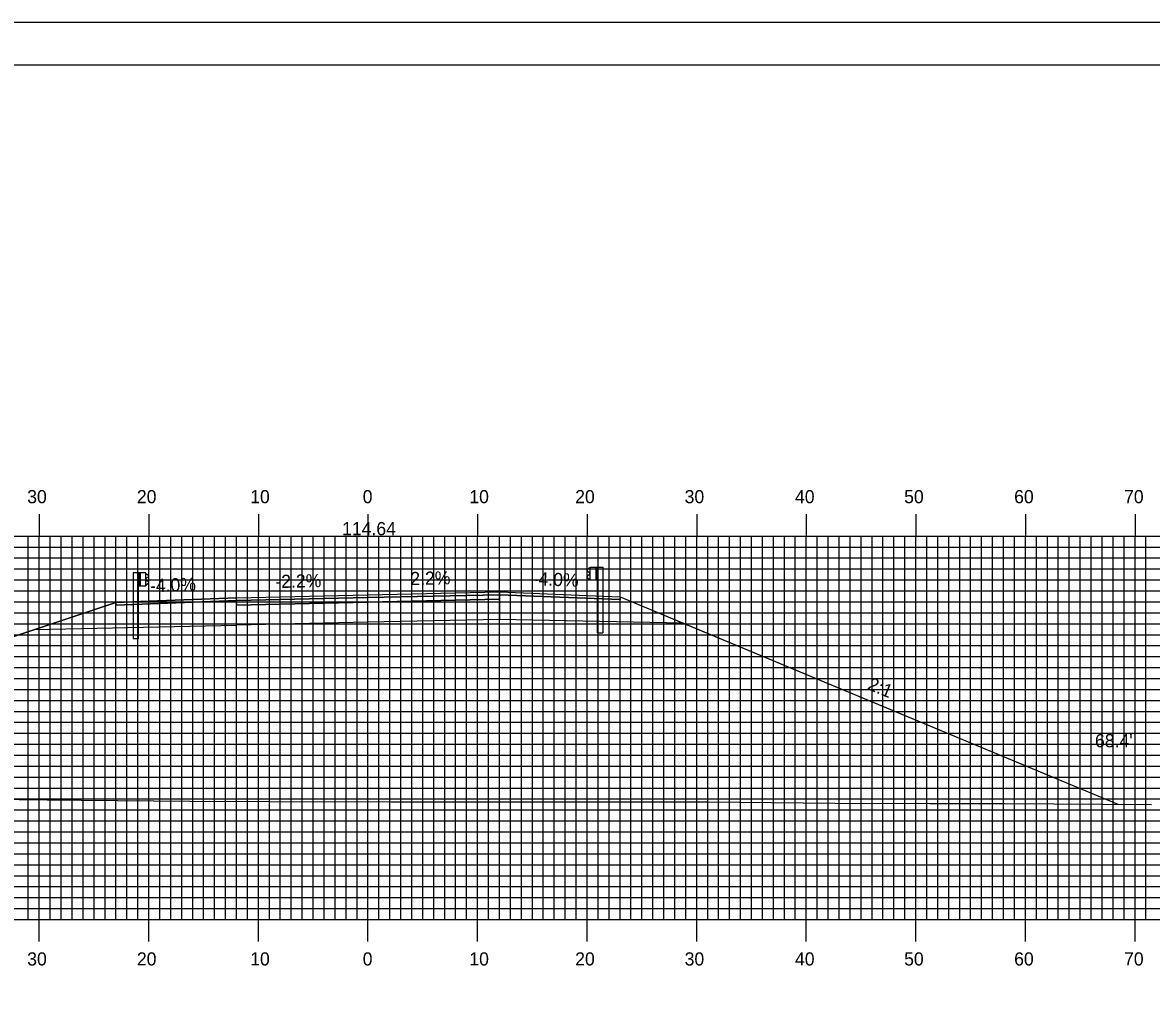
# Model space of a CAD drawing. Extents: x 1786582 to 1786926, y 442591 to 442811.
# Drawn here: x 1786716.6 to 1786819.6, y 442722 to 442810.5 of the extents above; entities that cross this region are included whole.
import ezdxf

# ---------------------------------------------------------------- set-up
doc = ezdxf.new("R2010")
doc.units = 0
for name, color, linetype in [('ANNOTATION', 7, 'Continuous'), ('BORDER', 7, 'Continuous'), ('D_Guardrail_Beam_Lt', 7, 'Continuous'), ('D_Guardrail_Beam_Rt', 7, 'Continuous'), ('D_Roadway_Centerline', 7, 'Continuous'), ('D_Roadway_Centerline_Text', 7, 'Continuous'), ('D_Roadway_Edge_Shoulder', 7, 'Continuous'), ('D_Roadway_Edge_TW', 7, 'Continuous'), ('D_Roadway_Pavement', 7, 'Continuous'), ('D_Roadway_SlopeLines', 7, 'Continuous'), ('D_Roadway_SubGrade', 7, 'Continuous'), ('D_Text_Standard', 7, 'Continuous'), ('H_V ANNOTATION', 7, 'Continuous'), ('MAJOR', 7, 'Continuous'), ('MINOR', 7, 'Continuous'), ('PLOT BOUNDARY', 7, 'Continuous'), ('S_Roadway_Centerline', 7, 'Continuous')]:
    doc.layers.add(name, color=color, linetype=linetype)

msp = doc.modelspace()

# ---------------------------------------------------------------- linework, layer by layer
at = {"layer": 'BORDER'}
msp.add_lwpolyline([(1786598.48, 442596.67), (1786918.48, 442596.67), (1786918.48, 442806.67), (1786598.48, 442806.67)], close=True, dxfattribs=at)
at = {"layer": 'D_Guardrail_Beam_Lt'}
for p, q in [((1786726.65, 442760.3), (1786726.65, 442754.3)), ((1786727.12, 442760.3), (1786726.65, 442760.3)), ((1786727.81, 442760.3), (1786727.12, 442760.3)), ((1786727.12, 442760.3), (1786727.12, 442759.14)), ((1786727.18, 442760.3), (1786727.18, 442759.14)), ((1786727.29, 442760.3), (1786727.29, 442759.14)), ((1786727.81, 442759.14), (1786727.81, 442760.3)), ((1786727.81, 442760.22), (1786727.88, 442760.21)), ((1786727.81, 442759.75), (1786727.81, 442759.68)), ((1786728.04, 442759.96), (1786727.85, 442759.82)), ((1786727.85, 442759.62), (1786728.04, 442759.48)), ((1786727.9, 442760.2), (1786728.04, 442760.1)), ((1786727.12, 442759.14), (1786727.81, 442759.14)), ((1786727.14, 442754.3), (1786727.14, 442759.14)), ((1786727.88, 442759.23), (1786727.81, 442759.22)), ((1786728.04, 442759.34), (1786727.9, 442759.24)), ((1786727.14, 442754.3), (1786726.65, 442754.3))]:
    msp.add_line(p, q, dxfattribs=at)
for centre, major_axis, start_param, end_param in [((1786727.89, 442759.75), (-0.0789, 0), 5.323254, 6.283185), ((1786727.89, 442759.68), (-0.0789, 0), 6.283185, 7.243116), ((1786727.87, 442760.16), (0.0417, 0), 0.959931, 1.376053), ((1786727.99, 442760.03), (0.0877, 0), 5.323254, 7.243116), ((1786727.87, 442759.27), (0.0417, 0), 4.907132, 5.323254), ((1786727.99, 442759.41), (0.0877, 0), 5.323254, 7.243116)]:
    msp.add_ellipse(centre, major_axis=major_axis, ratio=0.995501, start_param=start_param, end_param=end_param, dxfattribs=at)
at = {"layer": 'D_Guardrail_Beam_Rt'}
for p, q in [((1786768.26, 442760.73), (1786768.12, 442760.63)), ((1786768.35, 442760.75), (1786768.27, 442760.73)), ((1786768.35, 442760.83), (1786769.04, 442760.83)), ((1786768.35, 442759.66), (1786768.35, 442760.83)), ((1786768.87, 442760.83), (1786768.87, 442759.66)), ((1786768.97, 442760.83), (1786768.97, 442759.66)), ((1786769.04, 442760.83), (1786769.51, 442760.83)), ((1786769.04, 442760.83), (1786769.04, 442759.66)), ((1786769.51, 442760.83), (1786769.51, 442754.83)), ((1786768.12, 442760.48), (1786768.31, 442760.35)), ((1786768.31, 442760.15), (1786768.12, 442760.01)), ((1786768.12, 442759.87), (1786768.26, 442759.77)), ((1786768.27, 442759.76), (1786768.35, 442759.75)), ((1786768.34, 442760.28), (1786768.34, 442760.21)), ((1786769.04, 442759.66), (1786768.35, 442759.66)), ((1786769.02, 442754.83), (1786769.02, 442759.66)), ((1786769.02, 442754.83), (1786769.51, 442754.83))]:
    msp.add_line(p, q, dxfattribs=at)
for centre, major_axis, start_param, end_param in [((1786768.17, 442760.55), (-0.0877, 0), 5.323254, 7.243116), ((1786768.28, 442760.69), (-0.0417, 0), 4.907132, 5.323254), ((1786768.17, 442759.94), (-0.0877, 0), 5.323254, 7.243116), ((1786768.28, 442759.8), (-0.0417, 0), 0.959931, 1.376053), ((1786768.27, 442760.28), (0.0789, 0), 0, 0.959931), ((1786768.27, 442760.21), (0.0789, 0), 5.323254, 6.283185)]:
    msp.add_ellipse(centre, major_axis=major_axis, ratio=0.995501, start_param=start_param, end_param=end_param, dxfattribs=at)
at = {"layer": 'D_Roadway_Centerline'}
msp.add_lwpolyline([(1786673.07, 442740.26), (1786717.68, 442755.13), (1786725.08, 442757.6), (1786728.08, 442757.72), (1786736.08, 442758.04), (1786748.08, 442758.3), (1786760.08, 442758.57), (1786768.08, 442758.25), (1786771.08, 442758.13), (1786776.83, 442755.73), (1786816.52, 442739.19)], dxfattribs=at)
at = {"layer": 'D_Roadway_Edge_Shoulder'}
for points in [[(1786760.08, 442758.57), (1786768.08, 442758.25), (1786768.08, 442758.25), (1786771.08, 442758.13), (1786771.08, 442757.88), (1786760.08, 442758.32)], [(1786736.08, 442758.04), (1786728.08, 442757.72), (1786728.08, 442757.72), (1786725.08, 442757.6), (1786725.08, 442757.35), (1786736.08, 442757.79)]]:
    msp.add_lwpolyline(points, close=True, dxfattribs=at)
at = {"layer": 'D_Roadway_Edge_TW'}
msp.add_lwpolyline([(1786736.08, 442757.79), (1786736.08, 442758.04), (1786748.08, 442758.3), (1786760.08, 442758.57), (1786760.08, 442758.32), (1786748.08, 442758.05)], close=True, dxfattribs=at)
at = {"layer": 'D_Roadway_Pavement'}
msp.add_lwpolyline([(1786736.08, 442757.37), (1786736.08, 442757.79), (1786748.08, 442758.05), (1786760.08, 442758.32), (1786760.08, 442757.9), (1786748.08, 442757.64)], close=True, dxfattribs=at)
for points in [[(1786736.08, 442757.79), (1786736.08, 442757.37)], [(1786760.08, 442758.32), (1786760.08, 442757.9)]]:
    msp.add_lwpolyline(points, dxfattribs=at)
at = {"layer": 'D_Roadway_SlopeLines'}
for points in [[(1786725.08, 442757.6), (1786670.4, 442739.38)], [(1786771.08, 442758.13), (1786816.52, 442739.19)]]:
    msp.add_lwpolyline(points, dxfattribs=at)
at = {"layer": 'D_Roadway_SubGrade'}
for points in [[(1786736.08, 442757.37), (1786736.08, 442757.79), (1786725.08, 442757.35), (1786725.08, 442757.6), (1786717.68, 442755.13), (1786736.08, 442755.54)], [(1786736.08, 442755.54), (1786736.08, 442757.79), (1786736.08, 442757.37), (1786748.08, 442757.64), (1786760.08, 442757.9), (1786760.08, 442758.32), (1786760.08, 442756.07), (1786748.08, 442755.8)], [(1786760.08, 442757.9), (1786760.08, 442758.32), (1786771.08, 442757.88), (1786771.08, 442758.13), (1786776.83, 442755.73), (1786760.08, 442756.07)]]:
    msp.add_lwpolyline(points, close=True, dxfattribs=at)
at = {"layer": 'MAJOR'}
for p, q in [((1786718.08, 442765.67), (1786718.08, 442763.67)), ((1786728.08, 442765.67), (1786728.08, 442763.67)), ((1786738.08, 442765.67), (1786738.08, 442763.67)), ((1786748.08, 442765.67), (1786748.08, 442763.67)), ((1786758.08, 442765.67), (1786758.08, 442763.67)), ((1786768.08, 442765.67), (1786768.08, 442763.67)), ((1786778.08, 442765.67), (1786778.08, 442763.67)), ((1786788.08, 442765.67), (1786788.08, 442763.67)), ((1786798.08, 442765.67), (1786798.08, 442763.67)), ((1786808.08, 442765.67), (1786808.08, 442763.67)), ((1786818.08, 442765.67), (1786818.08, 442763.67)), ((1786608.08, 442763.67), (1786888.08, 442763.67)), ((1786608.08, 442763.67), (1786888.08, 442763.67)), ((1786718.08, 442728.67), (1786718.08, 442763.67)), ((1786728.08, 442728.67), (1786728.08, 442763.67)), ((1786738.08, 442728.67), (1786738.08, 442763.67)), ((1786748.08, 442728.67), (1786748.08, 442763.67)), ((1786758.08, 442728.67), (1786758.08, 442763.67)), ((1786768.08, 442728.67), (1786768.08, 442763.67)), ((1786778.08, 442728.67), (1786778.08, 442763.67)), ((1786788.08, 442728.67), (1786788.08, 442763.67)), ((1786798.08, 442728.67), (1786798.08, 442763.67)), ((1786808.08, 442728.67), (1786808.08, 442763.67)), ((1786818.08, 442728.67), (1786818.08, 442763.67)), ((1786608.08, 442758.67), (1786888.08, 442758.67)), ((1786608.08, 442753.67), (1786888.08, 442753.67)), ((1786608.08, 442748.67), (1786888.08, 442748.67)), ((1786608.08, 442743.67), (1786888.08, 442743.67)), ((1786608.08, 442738.67), (1786888.08, 442738.67)), ((1786608.08, 442733.67), (1786888.08, 442733.67)), ((1786608.08, 442728.67), (1786888.08, 442728.67)), ((1786608.08, 442728.67), (1786888.08, 442728.67)), ((1786718.08, 442726.66), (1786718.08, 442728.67)), ((1786728.08, 442726.66), (1786728.08, 442728.67)), ((1786738.08, 442726.66), (1786738.08, 442728.67)), ((1786748.08, 442726.66), (1786748.08, 442728.67)), ((1786758.08, 442726.66), (1786758.08, 442728.67)), ((1786768.08, 442726.66), (1786768.08, 442728.67)), ((1786778.08, 442726.66), (1786778.08, 442728.67)), ((1786788.08, 442726.66), (1786788.08, 442728.67)), ((1786798.08, 442726.66), (1786798.08, 442728.67)), ((1786808.08, 442726.66), (1786808.08, 442728.67)), ((1786818.08, 442726.66), (1786818.08, 442728.67))]:
    msp.add_line(p, q, dxfattribs=at)
at = {"layer": 'MINOR'}
for p, q in [((1786608.08, 442762.67), (1786888.08, 442762.67)), ((1786717.08, 442728.67), (1786717.08, 442763.67)), ((1786719.08, 442728.67), (1786719.08, 442763.67)), ((1786720.08, 442728.67), (1786720.08, 442763.67)), ((1786721.08, 442728.67), (1786721.08, 442763.67)), ((1786722.08, 442728.67), (1786722.08, 442763.67)), ((1786723.08, 442728.67), (1786723.08, 442763.67)), ((1786724.08, 442728.67), (1786724.08, 442763.67)), ((1786725.08, 442728.67), (1786725.08, 442763.67)), ((1786726.08, 442728.67), (1786726.08, 442763.67)), ((1786727.08, 442728.67), (1786727.08, 442763.67)), ((1786729.08, 442728.67), (1786729.08, 442763.67)), ((1786730.08, 442728.67), (1786730.08, 442763.67)), ((1786731.08, 442728.67), (1786731.08, 442763.67)), ((1786732.08, 442728.67), (1786732.08, 442763.67)), ((1786733.08, 442728.67), (1786733.08, 442763.67)), ((1786734.08, 442728.67), (1786734.08, 442763.67)), ((1786735.08, 442728.67), (1786735.08, 442763.67)), ((1786736.08, 442728.67), (1786736.08, 442763.67)), ((1786737.08, 442728.67), (1786737.08, 442763.67)), ((1786739.08, 442728.67), (1786739.08, 442763.67)), ((1786740.08, 442728.67), (1786740.08, 442763.67)), ((1786741.08, 442728.67), (1786741.08, 442763.67)), ((1786742.08, 442728.67), (1786742.08, 442763.67)), ((1786743.08, 442728.67), (1786743.08, 442763.67)), ((1786744.08, 442728.67), (1786744.08, 442763.67)), ((1786745.08, 442728.67), (1786745.08, 442763.67)), ((1786746.08, 442728.67), (1786746.08, 442763.67)), ((1786747.08, 442728.67), (1786747.08, 442763.67)), ((1786749.08, 442728.67), (1786749.08, 442763.67)), ((1786750.08, 442728.67), (1786750.08, 442763.67)), ((1786751.08, 442728.67), (1786751.08, 442763.67)), ((1786752.08, 442728.67), (1786752.08, 442763.67)), ((1786753.08, 442728.67), (1786753.08, 442763.67)), ((1786754.08, 442728.67), (1786754.08, 442763.67)), ((1786755.08, 442728.67), (1786755.08, 442763.67)), ((1786756.08, 442728.67), (1786756.08, 442763.67)), ((1786757.08, 442728.67), (1786757.08, 442763.67)), ((1786759.08, 442728.67), (1786759.08, 442763.67)), ((1786760.08, 442728.67), (1786760.08, 442763.67)), ((1786761.08, 442728.67), (1786761.08, 442763.67)), ((1786762.08, 442728.67), (1786762.08, 442763.67)), ((1786763.08, 442728.67), (1786763.08, 442763.67)), ((1786764.08, 442728.67), (1786764.08, 442763.67)), ((1786765.08, 442728.67), (1786765.08, 442763.67)), ((1786766.08, 442728.67), (1786766.08, 442763.67)), ((1786767.08, 442728.67), (1786767.08, 442763.67)), ((1786769.08, 442728.67), (1786769.08, 442763.67)), ((1786770.08, 442728.67), (1786770.08, 442763.67)), ((1786771.08, 442728.67), (1786771.08, 442763.67)), ((1786772.08, 442728.67), (1786772.08, 442763.67)), ((1786773.08, 442728.67), (1786773.08, 442763.67)), ((1786774.08, 442728.67), (1786774.08, 442763.67)), ((1786775.08, 442728.67), (1786775.08, 442763.67)), ((1786776.08, 442728.67), (1786776.08, 442763.67)), ((1786777.08, 442728.67), (1786777.08, 442763.67)), ((1786779.08, 442728.67), (1786779.08, 442763.67)), ((1786780.08, 442728.67), (1786780.08, 442763.67)), ((1786781.08, 442728.67), (1786781.08, 442763.67)), ((1786782.08, 442728.67), (1786782.08, 442763.67)), ((1786783.08, 442728.67), (1786783.08, 442763.67)), ((1786784.08, 442728.67), (1786784.08, 442763.67)), ((1786785.08, 442728.67), (1786785.08, 442763.67)), ((1786786.08, 442728.67), (1786786.08, 442763.67)), ((1786787.08, 442728.67), (1786787.08, 442763.67)), ((1786789.08, 442728.67), (1786789.08, 442763.67)), ((1786790.08, 442728.67), (1786790.08, 442763.67)), ((1786791.08, 442728.67), (1786791.08, 442763.67)), ((1786792.08, 442728.67), (1786792.08, 442763.67)), ((1786793.08, 442728.67), (1786793.08, 442763.67)), ((1786794.08, 442728.67), (1786794.08, 442763.67)), ((1786795.08, 442728.67), (1786795.08, 442763.67)), ((1786796.08, 442728.67), (1786796.08, 442763.67)), ((1786797.08, 442728.67), (1786797.08, 442763.67)), ((1786799.08, 442728.67), (1786799.08, 442763.67)), ((1786800.08, 442728.67), (1786800.08, 442763.67)), ((1786801.08, 442728.67), (1786801.08, 442763.67)), ((1786802.08, 442728.67), (1786802.08, 442763.67)), ((1786803.08, 442728.67), (1786803.08, 442763.67)), ((1786804.08, 442728.67), (1786804.08, 442763.67)), ((1786805.08, 442728.67), (1786805.08, 442763.67)), ((1786806.08, 442728.67), (1786806.08, 442763.67)), ((1786807.08, 442728.67), (1786807.08, 442763.67)), ((1786809.08, 442728.67), (1786809.08, 442763.67)), ((1786810.08, 442728.67), (1786810.08, 442763.67)), ((1786811.08, 442728.67), (1786811.08, 442763.67)), ((1786812.08, 442728.67), (1786812.08, 442763.67)), ((1786813.08, 442728.67), (1786813.08, 442763.67)), ((1786814.08, 442728.67), (1786814.08, 442763.67)), ((1786815.08, 442728.67), (1786815.08, 442763.67)), ((1786816.08, 442728.67), (1786816.08, 442763.67)), ((1786817.08, 442728.67), (1786817.08, 442763.67)), ((1786819.08, 442728.67), (1786819.08, 442763.67)), ((1786608.08, 442761.67), (1786888.08, 442761.67)), ((1786608.08, 442760.67), (1786888.08, 442760.67)), ((1786608.08, 442759.67), (1786888.08, 442759.67)), ((1786608.08, 442757.67), (1786888.08, 442757.67)), ((1786608.08, 442756.67), (1786888.08, 442756.67)), ((1786608.08, 442755.67), (1786888.08, 442755.67)), ((1786608.08, 442754.67), (1786888.08, 442754.67)), ((1786608.08, 442752.67), (1786888.08, 442752.67)), ((1786608.08, 442751.67), (1786888.08, 442751.67)), ((1786608.08, 442750.67), (1786888.08, 442750.67)), ((1786608.08, 442749.67), (1786888.08, 442749.67)), ((1786608.08, 442747.67), (1786888.08, 442747.67)), ((1786608.08, 442746.67), (1786888.08, 442746.67)), ((1786608.08, 442745.67), (1786888.08, 442745.67)), ((1786608.08, 442744.67), (1786888.08, 442744.67)), ((1786608.08, 442742.67), (1786888.08, 442742.67)), ((1786608.08, 442741.67), (1786888.08, 442741.67)), ((1786608.08, 442740.67), (1786888.08, 442740.67)), ((1786608.08, 442739.67), (1786888.08, 442739.67)), ((1786608.08, 442737.67), (1786888.08, 442737.67)), ((1786608.08, 442736.67), (1786888.08, 442736.67)), ((1786608.08, 442735.67), (1786888.08, 442735.67)), ((1786608.08, 442734.67), (1786888.08, 442734.67)), ((1786608.08, 442732.67), (1786888.08, 442732.67)), ((1786608.08, 442731.67), (1786888.08, 442731.67)), ((1786608.08, 442730.67), (1786888.08, 442730.67)), ((1786608.08, 442729.67), (1786888.08, 442729.67))]:
    msp.add_line(p, q, dxfattribs=at)
at = {"layer": 'PLOT BOUNDARY'}
msp.add_lwpolyline([(1786582.29, 442590.55), (1786922.29, 442590.55), (1786922.29, 442810.55), (1786582.29, 442810.55)], close=True, dxfattribs=at)
at = {"layer": 'S_Roadway_Centerline'}
msp.add_lwpolyline([(1786711.06, 442739.68), (1786718.81, 442739.58), (1786720.09, 442739.59), (1786721.89, 442739.55), (1786731.84, 442739.48), (1786739.08, 442739.44), (1786750.21, 442739.42), (1786759.17, 442739.41), (1786778.06, 442739.41), (1786778.66, 442739.4), (1786779.09, 442739.4), (1786790.7, 442739.28), (1786799.37, 442739.26), (1786806.24, 442739.25), (1786819.58, 442739.18)], dxfattribs=at)

# ---------------------------------------------------------------- texts
at = {"layer": 'ANNOTATION'}
for s, rotation, p in [('-4.0%', 2.2906, (1786728.21, 442758.53)), ('-2.2%', 1.2603, (1786739.64, 442758.92)), ('2.2%', 1.2603, (1786751.96, 442759.19)), ('-4.0%', 357.7094, (1786763.09, 442759.2)), ('2:1', 337.3801, (1786793.58, 442749.72))]:
    msp.add_text(s, height=1.2, rotation=rotation, dxfattribs=at).set_placement(p)
at = {"layer": 'D_Roadway_Centerline'}
for s, p in [('C', (1786748.07, 442758.3)), ('L', (1786748.08, 442758.3))]:
    msp.add_text(s, height=0.0146, dxfattribs=at).set_placement(p)
at = {"layer": 'D_Roadway_Centerline_Text'}
msp.add_text('114.64', height=1.2, dxfattribs=at).set_placement((1786745.72, 442763.75))
at = {"layer": 'D_Text_Standard'}
msp.add_text("68.4'", height=1.2, dxfattribs=at).set_placement((1786814.43, 442744.39))
at = {"layer": 'H_V ANNOTATION'}
for s, p in [('30', (1786716.98, 442766.67)), ('20', (1786726.99, 442766.67)), ('10', (1786737.33, 442766.67)), ('0', (1786747.6, 442766.67)), ('10', (1786757.33, 442766.67)), ('20', (1786766.99, 442766.67)), ('30', (1786776.98, 442766.67)), ('40', (1786787.05, 442766.67)), ('50', (1786797.01, 442766.67)), ('60', (1786807.05, 442766.67)), ('70', (1786817.08, 442766.67)), ('30', (1786716.98, 442724.47)), ('20', (1786726.99, 442724.47)), ('10', (1786737.33, 442724.47)), ('0', (1786747.6, 442724.47)), ('10', (1786757.33, 442724.47)), ('20', (1786766.99, 442724.47)), ('30', (1786776.98, 442724.47)), ('40', (1786787.05, 442724.47)), ('50', (1786797.01, 442724.47)), ('60', (1786807.05, 442724.47)), ('70', (1786817.08, 442724.47))]:
    msp.add_text(s, height=1.2, dxfattribs=at).set_placement(p)

doc.saveas('drawing.dxf')
